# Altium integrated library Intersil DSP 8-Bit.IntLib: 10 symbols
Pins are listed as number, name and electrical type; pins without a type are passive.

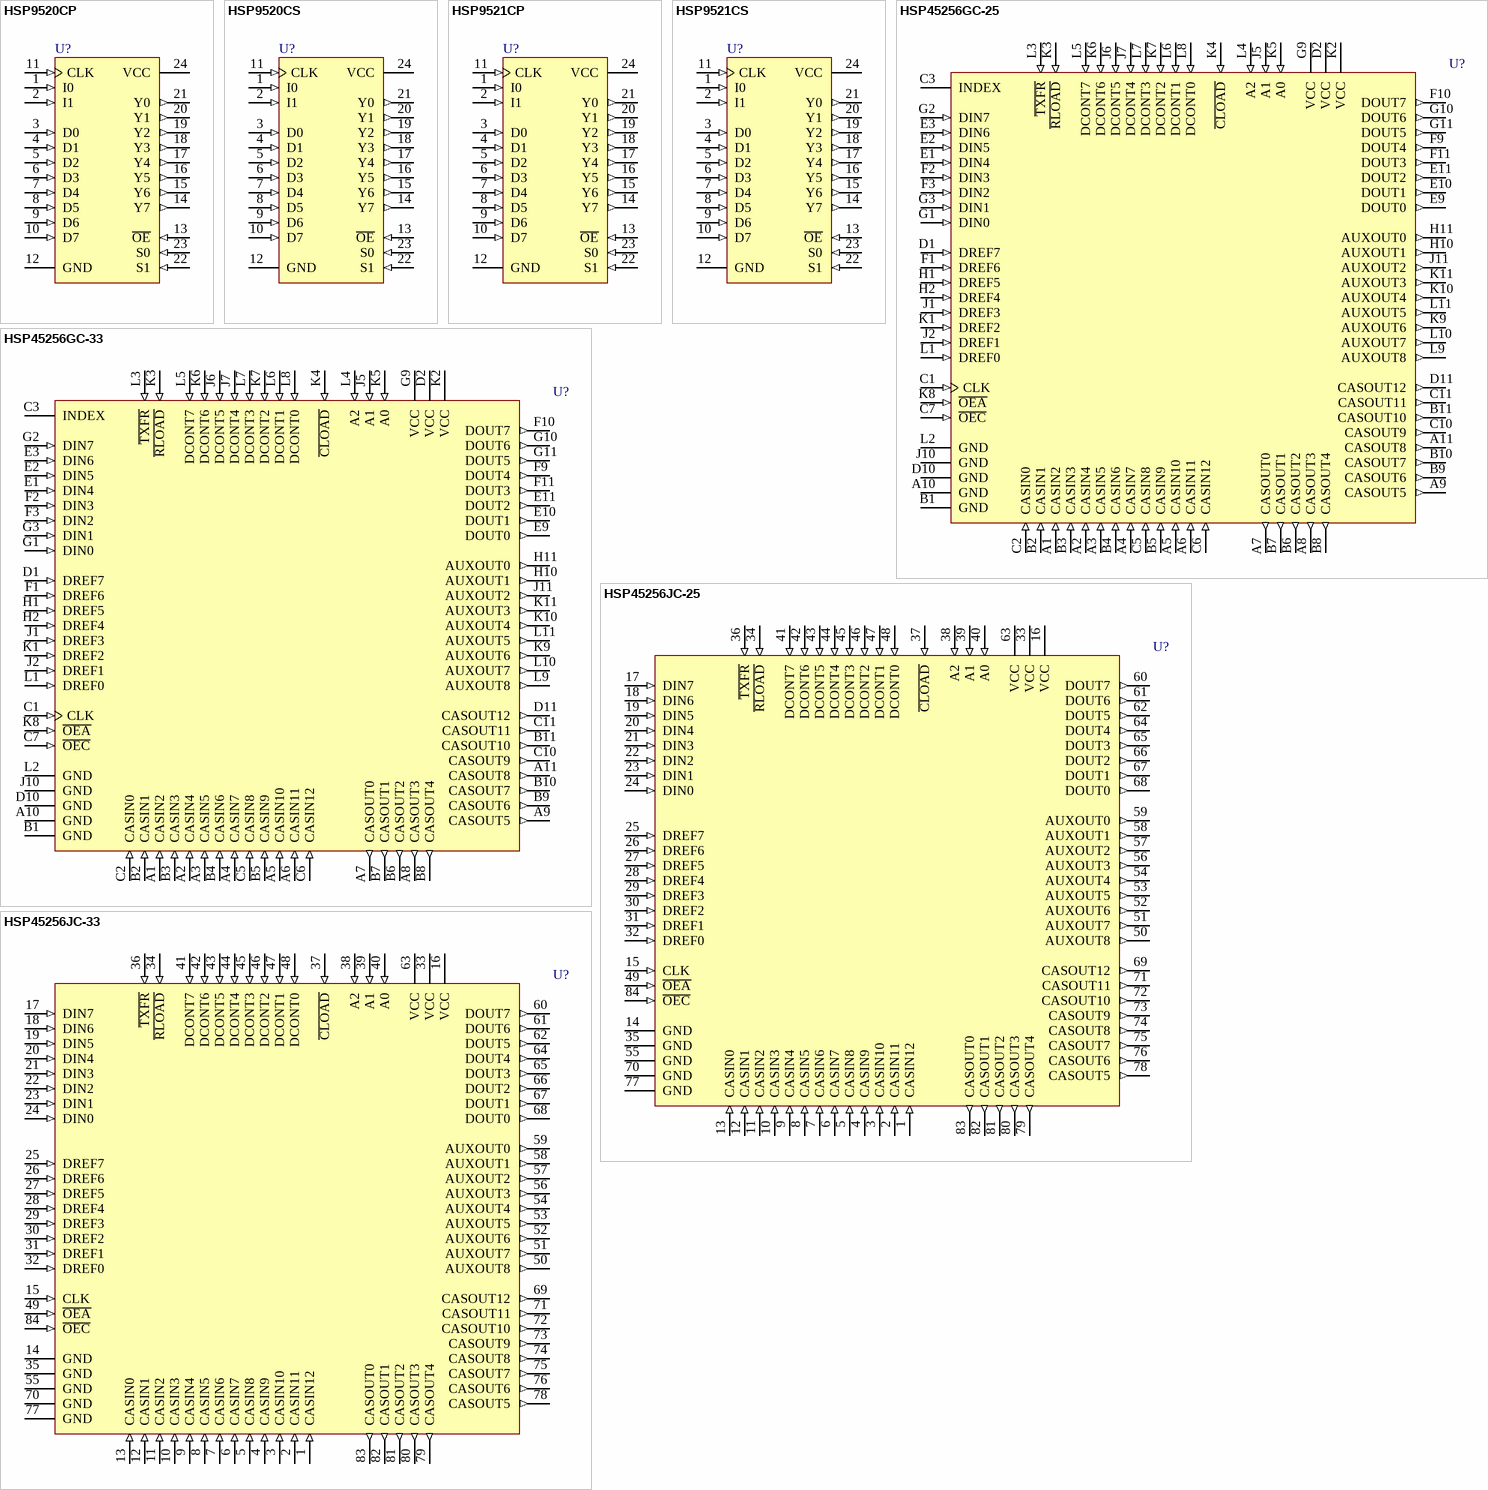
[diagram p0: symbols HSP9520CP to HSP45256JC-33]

## HSP9520CP
designator U?
Multilevel Pipeline Registers
footprint E24.3 (DIP, 24-Leads, Row Spacing 7.62mm, Pitch 2.54mm, Body 31.88x6.61mm)
3D model E24_3 (DIP, 24-Pin, Row Spacing 7.62 mm, Pitch 2.54 mm)
pins: 1 I0 (in), 2 I1 (in), 3 D0 (in), 4 D1 (in), 5 D2 (in), 6 D3 (in), 7 D4 (in), 8 D5 (in), 9 D6 (in), 10 D7 (in), 11 CLK (in), 12 GND (power), 13 ~{OE} (in), 14 Y7 (out), 15 Y6 (out), 16 Y5 (out), 17 Y4 (out), 18 Y3 (out), 19 Y2 (out), 20 Y1 (out), 21 Y0 (out), 22 S1 (in), 23 S0 (in), 24 VCC (power)

## HSP9520CS
designator U?
Multilevel Pipeline Registers
footprint M24.3_N (SOIC, 24-Leads, Body 15.4x7.5mm, Pitch 1.27mm, IPC Medium Density)
footprint M24.3_L (SOIC, 24-Leads, Body 15.4x7.5mm, Pitch 1.27mm, IPC High Density)
footprint M24.3_M (SOIC, 24-Leads, Body 15.4x7.5mm, Pitch 1.27mm, IPC Low Density)
3D model M24_3 (24-Pin Small Outline Integrated Circuit 1.27 mm Pitch)
pins: 1 I0 (in), 2 I1 (in), 3 D0 (in), 4 D1 (in), 5 D2 (in), 6 D3 (in), 7 D4 (in), 8 D5 (in), 9 D6 (in), 10 D7 (in), 11 CLK (in), 12 GND (power), 13 ~{OE} (in), 14 Y7 (out), 15 Y6 (out), 16 Y5 (out), 17 Y4 (out), 18 Y3 (out), 19 Y2 (out), 20 Y1 (out), 21 Y0 (out), 22 S1 (in), 23 S0 (in), 24 VCC (power)

## HSP9521CP
designator U?
Multilevel Pipeline Registers
footprint E24.3 (DIP, 24-Leads, Row Spacing 7.62mm, Pitch 2.54mm, Body 31.88x6.61mm)
3D model E24_3 (DIP, 24-Pin, Row Spacing 7.62 mm, Pitch 2.54 mm)
pins: 1 I0 (in), 2 I1 (in), 3 D0 (in), 4 D1 (in), 5 D2 (in), 6 D3 (in), 7 D4 (in), 8 D5 (in), 9 D6 (in), 10 D7 (in), 11 CLK (in), 12 GND (power), 13 ~{OE} (in), 14 Y7 (out), 15 Y6 (out), 16 Y5 (out), 17 Y4 (out), 18 Y3 (out), 19 Y2 (out), 20 Y1 (out), 21 Y0 (out), 22 S1 (in), 23 S0 (in), 24 VCC (power)

## HSP9521CS
designator U?
Multilevel Pipeline Registers
footprint M24.3_N (SOIC, 24-Leads, Body 15.4x7.5mm, Pitch 1.27mm, IPC Medium Density)
footprint M24.3_L (SOIC, 24-Leads, Body 15.4x7.5mm, Pitch 1.27mm, IPC High Density)
footprint M24.3_M (SOIC, 24-Leads, Body 15.4x7.5mm, Pitch 1.27mm, IPC Low Density)
3D model M24_3 (24-Pin Small Outline Integrated Circuit 1.27 mm Pitch)
pins: 1 I0 (in), 2 I1 (in), 3 D0 (in), 4 D1 (in), 5 D2 (in), 6 D3 (in), 7 D4 (in), 8 D5 (in), 9 D6 (in), 10 D7 (in), 11 CLK (in), 12 GND (power), 13 ~{OE} (in), 14 Y7 (out), 15 Y6 (out), 16 Y5 (out), 17 Y4 (out), 18 Y3 (out), 19 Y2 (out), 20 Y1 (out), 21 Y0 (out), 22 S1 (in), 23 S0 (in), 24 VCC (power)

## HSP45256GC-25
designator U?
Binary Correlator
footprint G85.A (PGA, 85-Leads, Body 29.5x29.5mm, Pitch 2.54mm)
3D model HSP45256-G85_A (85-Pin Pin Grid Array 2.54 mm Pitch)
pins: A1 CASIN2 (in), A2 CASIN4 (in), A3 CASIN5 (in), A4 CASIN7 (in), A5 CASIN10 (in), A6 CASIN11 (in), A7 CASOUT0 (out), A8 CASOUT3 (out), A9 CASOUT5 (out), A10 GND (power), A11 CASOUT8 (out), B1 GND (power), B2 CASIN1 (in), B3 CASIN3 (in), B4 CASIN6 (in), B5 CASIN9 (in), B6 CASOUT2 (out), B7 CASOUT1 (out), B8 CASOUT4 (out), B9 CASOUT6 (out), B10 CASOUT7 (out), B11 CASOUT10 (out), C1 CLK (in), C2 CASIN0 (in), C3 INDEX, C5 CASIN8 (in), C6 CASIN12 (in), C7 ~{OEC} (in), C10 CASOUT9 (out), C11 CASOUT11 (out), D1 DREF7 (in), D2 VCC (power), D10 GND (power), D11 CASOUT12 (out), E1 DIN4 (in), E2 DIN5 (in), E3 DIN6 (in), E9 DOUT0 (out), E10 DOUT1 (out), E11 DOUT2 (out), F1 DREF6 (in), F2 DIN3 (in), F3 DIN2 (in), F9 DOUT4 (out), F10 DOUT7 (out), F11 DOUT3 (out), G1 DIN0 (in), G2 DIN7 (in), G3 DIN1 (in), G9 VCC (power), G10 DOUT6 (out), G11 DOUT5 (out), H1 DREF5 (in), H2 DREF4 (in), H10 AUXOUT1 (out), H11 AUXOUT0 (out), J1 DREF3 (in), J2 DREF1 (in), J5 A1 (in), J6 DCONT5 (in), J7 DCONT4 (in), J10 GND (power), J11 AUXOUT2 (out), K1 DREF2 (in), K2 VCC (power), K3 ~{RLOAD} (in), K4 ~{CLOAD} (in), K5 A0 (in), K6 DCONT6 (in), K7 DCONT2 (in), K8 ~{OEA} (in), K9 AUXOUT6 (out), K10 AUXOUT4 (out), K11 AUXOUT3 (out), L1 DREF0 (in), L2 GND (power), L3 ~{TXFR} (in), L4 A2 (in), L5 DCONT7 (in), L6 DCONT1 (in), L7 DCONT3 (in), L8 DCONT0 (in), L9 AUXOUT8 (out), L10 AUXOUT7 (out), L11 AUXOUT5 (out)

## HSP45256GC-33
designator U?
Binary Correlator
footprint G85.A (PGA, 85-Leads, Body 29.5x29.5mm, Pitch 2.54mm)
3D model HSP45256-G85_A (85-Pin Pin Grid Array 2.54 mm Pitch)
pins: A1 CASIN2 (in), A2 CASIN4 (in), A3 CASIN5 (in), A4 CASIN7 (in), A5 CASIN10 (in), A6 CASIN11 (in), A7 CASOUT0 (out), A8 CASOUT3 (out), A9 CASOUT5 (out), A10 GND (power), A11 CASOUT8 (out), B1 GND (power), B2 CASIN1 (in), B3 CASIN3 (in), B4 CASIN6 (in), B5 CASIN9 (in), B6 CASOUT2 (out), B7 CASOUT1 (out), B8 CASOUT4 (out), B9 CASOUT6 (out), B10 CASOUT7 (out), B11 CASOUT10 (out), C1 CLK (in), C2 CASIN0 (in), C3 INDEX, C5 CASIN8 (in), C6 CASIN12 (in), C7 ~{OEC} (in), C10 CASOUT9 (out), C11 CASOUT11 (out), D1 DREF7 (in), D2 VCC (power), D10 GND (power), D11 CASOUT12 (out), E1 DIN4 (in), E2 DIN5 (in), E3 DIN6 (in), E9 DOUT0 (out), E10 DOUT1 (out), E11 DOUT2 (out), F1 DREF6 (in), F2 DIN3 (in), F3 DIN2 (in), F9 DOUT4 (out), F10 DOUT7 (out), F11 DOUT3 (out), G1 DIN0 (in), G2 DIN7 (in), G3 DIN1 (in), G9 VCC (power), G10 DOUT6 (out), G11 DOUT5 (out), H1 DREF5 (in), H2 DREF4 (in), H10 AUXOUT1 (out), H11 AUXOUT0 (out), J1 DREF3 (in), J2 DREF1 (in), J5 A1 (in), J6 DCONT5 (in), J7 DCONT4 (in), J10 GND (power), J11 AUXOUT2 (out), K1 DREF2 (in), K2 VCC (power), K3 ~{RLOAD} (in), K4 ~{CLOAD} (in), K5 A0 (in), K6 DCONT6 (in), K7 DCONT2 (in), K8 ~{OEA} (in), K9 AUXOUT6 (out), K10 AUXOUT4 (out), K11 AUXOUT3 (out), L1 DREF0 (in), L2 GND (power), L3 ~{TXFR} (in), L4 A2 (in), L5 DCONT7 (in), L6 DCONT1 (in), L7 DCONT3 (in), L8 DCONT0 (in), L9 AUXOUT8 (out), L10 AUXOUT7 (out), L11 AUXOUT5 (out)

## HSP45256JC-25
designator U?
Binary Correlator
footprint N84.1.15_N (Leaded Chip Carrier, 84-Leads, Body 29.3x29.3mm, Pitch 1.27mm, IPC Medium Density)
footprint N84.1.15_L (Leaded Chip Carrier, 84-Leads, Body 29.3x29.3mm, Pitch 1.27mm, IPC High Density)
footprint N84.1.15_M (Leaded Chip Carrier, 84-Leads, Body 29.3x29.3mm, Pitch 1.27mm, IPC Low Density)
3D model HSP45256-N84_1_15 (84-Pin Leaded Chip Carrier 1.27 mm Pitch)
pins: 1 CASIN12 (in), 2 CASIN11 (in), 3 CASIN10 (in), 4 CASIN9 (in), 5 CASIN8 (in), 6 CASIN7 (in), 7 CASIN6 (in), 8 CASIN5 (in), 9 CASIN4 (in), 10 CASIN3 (in), 11 CASIN2 (in), 12 CASIN1 (in), 13 CASIN0 (in), 14 GND (power), 15 CLK (in), 16 VCC (power), 17 DIN7 (in), 18 DIN6 (in), 19 DIN5 (in), 20 DIN4 (in), 21 DIN3 (in), 22 DIN2 (in), 23 DIN1 (in), 24 DIN0 (in), 25 DREF7 (in), 26 DREF6 (in), 27 DREF5 (in), 28 DREF4 (in), 29 DREF3 (in), 30 DREF2 (in), 31 DREF1 (in), 32 DREF0 (in), 33 VCC (power), 34 ~{RLOAD} (in), 35 GND (power), 36 ~{TXFR} (in), 37 ~{CLOAD} (in), 38 A2 (in), 39 A1 (in), 40 A0 (in), 41 DCONT7 (in), 42 DCONT6 (in), 43 DCONT5 (in), 44 DCONT4 (in), 45 DCONT3 (in), 46 DCONT2 (in), 47 DCONT1 (in), 48 DCONT0 (in), 49 ~{OEA} (in), 50 AUXOUT8 (out), 51 AUXOUT7 (out), 52 AUXOUT6 (out), 53 AUXOUT5 (out), 54 AUXOUT4 (out), 55 GND (power), 56 AUXOUT3 (out), 57 AUXOUT2 (out), 58 AUXOUT1 (out), 59 AUXOUT0 (out), 60 DOUT7 (out), 61 DOUT6 (out), 62 DOUT5 (out), 63 VCC (power), 64 DOUT4 (out), 65 DOUT3 (out), 66 DOUT2 (out), 67 DOUT1 (out), 68 DOUT0 (out), 69 CASOUT12 (out), 70 GND (power), 71 CASOUT11 (out), 72 CASOUT10 (out), 73 CASOUT9 (out), 74 CASOUT8 (out), 75 CASOUT7 (out), 76 CASOUT6 (out), 77 GND (power), 78 CASOUT5 (out), 79 CASOUT4 (out), 80 CASOUT3 (out), 81 CASOUT2 (out), 82 CASOUT1 (out), 83 CASOUT0 (out), 84 ~{OEC} (in)

## HSP45256JC-33
designator U?
Binary Correlator
footprint N84.1.15_N (Leaded Chip Carrier, 84-Leads, Body 29.3x29.3mm, Pitch 1.27mm, IPC Medium Density)
footprint N84.1.15_L (Leaded Chip Carrier, 84-Leads, Body 29.3x29.3mm, Pitch 1.27mm, IPC High Density)
footprint N84.1.15_M (Leaded Chip Carrier, 84-Leads, Body 29.3x29.3mm, Pitch 1.27mm, IPC Low Density)
3D model HSP45256-N84_1_15 (84-Pin Leaded Chip Carrier 1.27 mm Pitch)
pins: 1 CASIN12 (in), 2 CASIN11 (in), 3 CASIN10 (in), 4 CASIN9 (in), 5 CASIN8 (in), 6 CASIN7 (in), 7 CASIN6 (in), 8 CASIN5 (in), 9 CASIN4 (in), 10 CASIN3 (in), 11 CASIN2 (in), 12 CASIN1 (in), 13 CASIN0 (in), 14 GND (power), 15 CLK (in), 16 VCC (power), 17 DIN7 (in), 18 DIN6 (in), 19 DIN5 (in), 20 DIN4 (in), 21 DIN3 (in), 22 DIN2 (in), 23 DIN1 (in), 24 DIN0 (in), 25 DREF7 (in), 26 DREF6 (in), 27 DREF5 (in), 28 DREF4 (in), 29 DREF3 (in), 30 DREF2 (in), 31 DREF1 (in), 32 DREF0 (in), 33 VCC (power), 34 ~{RLOAD} (in), 35 GND (power), 36 ~{TXFR} (in), 37 ~{CLOAD} (in), 38 A2 (in), 39 A1 (in), 40 A0 (in), 41 DCONT7 (in), 42 DCONT6 (in), 43 DCONT5 (in), 44 DCONT4 (in), 45 DCONT3 (in), 46 DCONT2 (in), 47 DCONT1 (in), 48 DCONT0 (in), 49 ~{OEA} (in), 50 AUXOUT8 (out), 51 AUXOUT7 (out), 52 AUXOUT6 (out), 53 AUXOUT5 (out), 54 AUXOUT4 (out), 55 GND (power), 56 AUXOUT3 (out), 57 AUXOUT2 (out), 58 AUXOUT1 (out), 59 AUXOUT0 (out), 60 DOUT7 (out), 61 DOUT6 (out), 62 DOUT5 (out), 63 VCC (power), 64 DOUT4 (out), 65 DOUT3 (out), 66 DOUT2 (out), 67 DOUT1 (out), 68 DOUT0 (out), 69 CASOUT12 (out), 70 GND (power), 71 CASOUT11 (out), 72 CASOUT10 (out), 73 CASOUT9 (out), 74 CASOUT8 (out), 75 CASOUT7 (out), 76 CASOUT6 (out), 77 GND (power), 78 CASOUT5 (out), 79 CASOUT4 (out), 80 CASOUT3 (out), 81 CASOUT2 (out), 82 CASOUT1 (out), 83 CASOUT0 (out), 84 ~{OEC} (in)

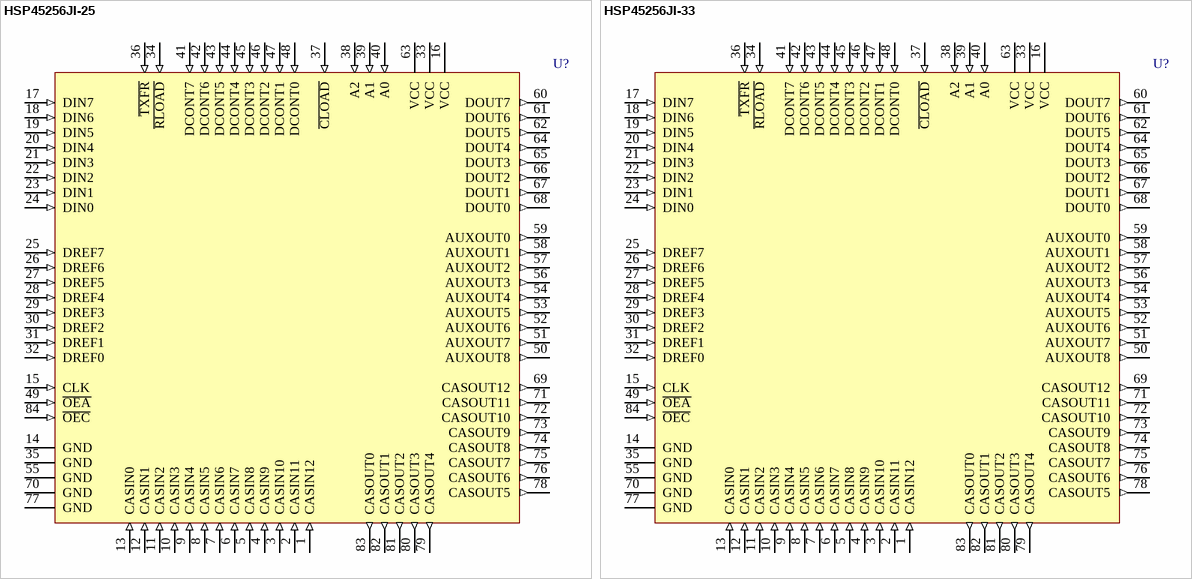
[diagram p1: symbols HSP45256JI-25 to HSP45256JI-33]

## HSP45256JI-25
designator U?
Binary Correlator
footprint N84.1.15_N (Leaded Chip Carrier, 84-Leads, Body 29.3x29.3mm, Pitch 1.27mm, IPC Medium Density)
footprint N84.1.15_L (Leaded Chip Carrier, 84-Leads, Body 29.3x29.3mm, Pitch 1.27mm, IPC High Density)
footprint N84.1.15_M (Leaded Chip Carrier, 84-Leads, Body 29.3x29.3mm, Pitch 1.27mm, IPC Low Density)
3D model HSP45256-N84_1_15 (84-Pin Leaded Chip Carrier 1.27 mm Pitch)
pins: 1 CASIN12 (in), 2 CASIN11 (in), 3 CASIN10 (in), 4 CASIN9 (in), 5 CASIN8 (in), 6 CASIN7 (in), 7 CASIN6 (in), 8 CASIN5 (in), 9 CASIN4 (in), 10 CASIN3 (in), 11 CASIN2 (in), 12 CASIN1 (in), 13 CASIN0 (in), 14 GND (power), 15 CLK (in), 16 VCC (power), 17 DIN7 (in), 18 DIN6 (in), 19 DIN5 (in), 20 DIN4 (in), 21 DIN3 (in), 22 DIN2 (in), 23 DIN1 (in), 24 DIN0 (in), 25 DREF7 (in), 26 DREF6 (in), 27 DREF5 (in), 28 DREF4 (in), 29 DREF3 (in), 30 DREF2 (in), 31 DREF1 (in), 32 DREF0 (in), 33 VCC (power), 34 ~{RLOAD} (in), 35 GND (power), 36 ~{TXFR} (in), 37 ~{CLOAD} (in), 38 A2 (in), 39 A1 (in), 40 A0 (in), 41 DCONT7 (in), 42 DCONT6 (in), 43 DCONT5 (in), 44 DCONT4 (in), 45 DCONT3 (in), 46 DCONT2 (in), 47 DCONT1 (in), 48 DCONT0 (in), 49 ~{OEA} (in), 50 AUXOUT8 (out), 51 AUXOUT7 (out), 52 AUXOUT6 (out), 53 AUXOUT5 (out), 54 AUXOUT4 (out), 55 GND (power), 56 AUXOUT3 (out), 57 AUXOUT2 (out), 58 AUXOUT1 (out), 59 AUXOUT0 (out), 60 DOUT7 (out), 61 DOUT6 (out), 62 DOUT5 (out), 63 VCC (power), 64 DOUT4 (out), 65 DOUT3 (out), 66 DOUT2 (out), 67 DOUT1 (out), 68 DOUT0 (out), 69 CASOUT12 (out), 70 GND (power), 71 CASOUT11 (out), 72 CASOUT10 (out), 73 CASOUT9 (out), 74 CASOUT8 (out), 75 CASOUT7 (out), 76 CASOUT6 (out), 77 GND (power), 78 CASOUT5 (out), 79 CASOUT4 (out), 80 CASOUT3 (out), 81 CASOUT2 (out), 82 CASOUT1 (out), 83 CASOUT0 (out), 84 ~{OEC} (in)

## HSP45256JI-33
designator U?
Binary Correlator
footprint N84.1.15_N (Leaded Chip Carrier, 84-Leads, Body 29.3x29.3mm, Pitch 1.27mm, IPC Medium Density)
footprint N84.1.15_L (Leaded Chip Carrier, 84-Leads, Body 29.3x29.3mm, Pitch 1.27mm, IPC High Density)
footprint N84.1.15_M (Leaded Chip Carrier, 84-Leads, Body 29.3x29.3mm, Pitch 1.27mm, IPC Low Density)
3D model HSP45256-N84_1_15 (84-Pin Leaded Chip Carrier 1.27 mm Pitch)
pins: 1 CASIN12 (in), 2 CASIN11 (in), 3 CASIN10 (in), 4 CASIN9 (in), 5 CASIN8 (in), 6 CASIN7 (in), 7 CASIN6 (in), 8 CASIN5 (in), 9 CASIN4 (in), 10 CASIN3 (in), 11 CASIN2 (in), 12 CASIN1 (in), 13 CASIN0 (in), 14 GND (power), 15 CLK (in), 16 VCC (power), 17 DIN7 (in), 18 DIN6 (in), 19 DIN5 (in), 20 DIN4 (in), 21 DIN3 (in), 22 DIN2 (in), 23 DIN1 (in), 24 DIN0 (in), 25 DREF7 (in), 26 DREF6 (in), 27 DREF5 (in), 28 DREF4 (in), 29 DREF3 (in), 30 DREF2 (in), 31 DREF1 (in), 32 DREF0 (in), 33 VCC (power), 34 ~{RLOAD} (in), 35 GND (power), 36 ~{TXFR} (in), 37 ~{CLOAD} (in), 38 A2 (in), 39 A1 (in), 40 A0 (in), 41 DCONT7 (in), 42 DCONT6 (in), 43 DCONT5 (in), 44 DCONT4 (in), 45 DCONT3 (in), 46 DCONT2 (in), 47 DCONT1 (in), 48 DCONT0 (in), 49 ~{OEA} (in), 50 AUXOUT8 (out), 51 AUXOUT7 (out), 52 AUXOUT6 (out), 53 AUXOUT5 (out), 54 AUXOUT4 (out), 55 GND (power), 56 AUXOUT3 (out), 57 AUXOUT2 (out), 58 AUXOUT1 (out), 59 AUXOUT0 (out), 60 DOUT7 (out), 61 DOUT6 (out), 62 DOUT5 (out), 63 VCC (power), 64 DOUT4 (out), 65 DOUT3 (out), 66 DOUT2 (out), 67 DOUT1 (out), 68 DOUT0 (out), 69 CASOUT12 (out), 70 GND (power), 71 CASOUT11 (out), 72 CASOUT10 (out), 73 CASOUT9 (out), 74 CASOUT8 (out), 75 CASOUT7 (out), 76 CASOUT6 (out), 77 GND (power), 78 CASOUT5 (out), 79 CASOUT4 (out), 80 CASOUT3 (out), 81 CASOUT2 (out), 82 CASOUT1 (out), 83 CASOUT0 (out), 84 ~{OEC} (in)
